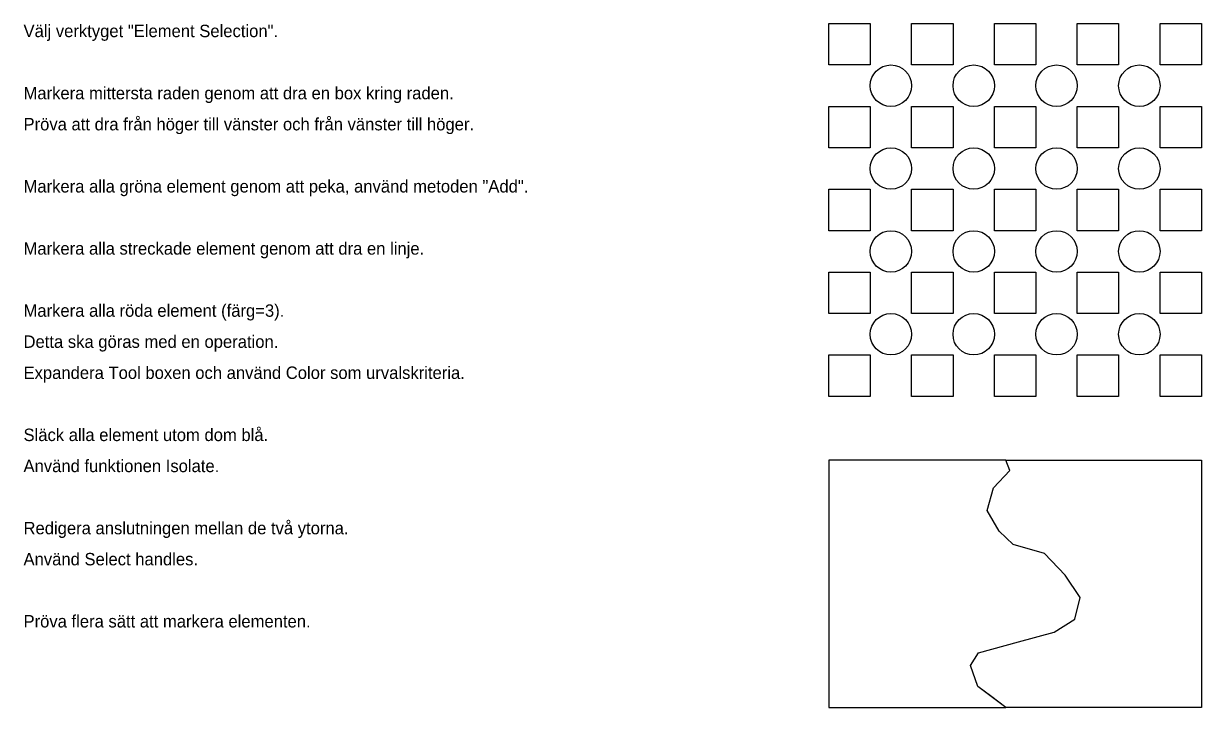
# Model space of a CAD drawing. Extents: x 1517706.2 to 1517734.6, y 6495359.5 to 6495376.
import ezdxf

# ---------------------------------------------------------------- set-up
doc = ezdxf.new("R2010")
doc.units = 0
doc.layers.add('Instruktioner', color=7, linetype='Continuous')
doc.layers.add('Lager 1', color=7, linetype='Continuous')

msp = doc.modelspace()

# ---------------------------------------------------------------- linework, layer by layer
at = {"layer": 'Lager 1'}
for points in [[(1517725.643, 6495375.967), (1517726.643, 6495375.967), (1517726.643, 6495374.967), (1517725.643, 6495374.967)], [(1517727.643, 6495375.967), (1517728.643, 6495375.967), (1517728.643, 6495374.967), (1517727.643, 6495374.967)], [(1517729.643, 6495375.967), (1517730.643, 6495375.967), (1517730.643, 6495374.967), (1517729.643, 6495374.967)], [(1517731.643, 6495375.967), (1517732.643, 6495375.967), (1517732.643, 6495374.967), (1517731.643, 6495374.967)], [(1517733.643, 6495375.967), (1517734.643, 6495375.967), (1517734.643, 6495374.967), (1517733.643, 6495374.967)], [(1517725.643, 6495373.967), (1517726.643, 6495373.967), (1517726.643, 6495372.967), (1517725.643, 6495372.967)], [(1517727.643, 6495373.967), (1517728.643, 6495373.967), (1517728.643, 6495372.967), (1517727.643, 6495372.967)], [(1517729.643, 6495373.967), (1517730.643, 6495373.967), (1517730.643, 6495372.967), (1517729.643, 6495372.967)], [(1517731.643, 6495373.967), (1517732.643, 6495373.967), (1517732.643, 6495372.967), (1517731.643, 6495372.967)], [(1517733.643, 6495373.967), (1517734.643, 6495373.967), (1517734.643, 6495372.967), (1517733.643, 6495372.967)], [(1517725.643, 6495371.967), (1517726.643, 6495371.967), (1517726.643, 6495370.967), (1517725.643, 6495370.967)], [(1517727.643, 6495371.967), (1517728.643, 6495371.967), (1517728.643, 6495370.967), (1517727.643, 6495370.967)], [(1517729.643, 6495371.967), (1517730.643, 6495371.967), (1517730.643, 6495370.967), (1517729.643, 6495370.967)], [(1517731.643, 6495371.967), (1517732.643, 6495371.967), (1517732.643, 6495370.967), (1517731.643, 6495370.967)], [(1517733.643, 6495371.967), (1517734.643, 6495371.967), (1517734.643, 6495370.967), (1517733.643, 6495370.967)], [(1517725.643, 6495369.967), (1517726.643, 6495369.967), (1517726.643, 6495368.967), (1517725.643, 6495368.967)], [(1517727.643, 6495369.967), (1517728.643, 6495369.967), (1517728.643, 6495368.967), (1517727.643, 6495368.967)], [(1517729.643, 6495369.967), (1517730.643, 6495369.967), (1517730.643, 6495368.967), (1517729.643, 6495368.967)], [(1517731.643, 6495369.967), (1517732.643, 6495369.967), (1517732.643, 6495368.967), (1517731.643, 6495368.967)], [(1517733.643, 6495369.967), (1517734.643, 6495369.967), (1517734.643, 6495368.967), (1517733.643, 6495368.967)], [(1517725.643, 6495367.967), (1517726.643, 6495367.967), (1517726.643, 6495366.967), (1517725.643, 6495366.967)], [(1517727.643, 6495367.967), (1517728.643, 6495367.967), (1517728.643, 6495366.967), (1517727.643, 6495366.967)], [(1517729.643, 6495367.967), (1517730.643, 6495367.967), (1517730.643, 6495366.967), (1517729.643, 6495366.967)], [(1517731.643, 6495367.967), (1517732.643, 6495367.967), (1517732.643, 6495366.967), (1517731.643, 6495366.967)], [(1517733.643, 6495367.967), (1517734.643, 6495367.967), (1517734.643, 6495366.967), (1517733.643, 6495366.967)], [(1517729.916, 6495365.426), (1517725.643, 6495365.426), (1517725.643, 6495359.459), (1517729.916, 6495359.459), (1517729.241, 6495359.966), (1517729.067, 6495360.471), (1517729.26, 6495360.775), (1517730.224, 6495361.041), (1517731.088, 6495361.28), (1517731.584, 6495361.586), (1517731.716, 6495362.109), (1517731.354, 6495362.65), (1517730.856, 6495363.177), (1517730.096, 6495363.394), (1517729.756, 6495363.716), (1517729.471, 6495364.212), (1517729.622, 6495364.764), (1517730.014, 6495365.18)], [(1517729.916, 6495365.426), (1517734.643, 6495365.426), (1517734.643, 6495359.459), (1517729.916, 6495359.459), (1517729.579, 6495359.713), (1517729.241, 6495359.966), (1517729.067, 6495360.471), (1517729.26, 6495360.775), (1517730.224, 6495361.041), (1517731.088, 6495361.28), (1517731.584, 6495361.586), (1517731.716, 6495362.109), (1517731.354, 6495362.65), (1517730.856, 6495363.177), (1517730.096, 6495363.394), (1517729.756, 6495363.716), (1517729.471, 6495364.212), (1517729.622, 6495364.764), (1517730.014, 6495365.18)]]:
    msp.add_lwpolyline(points, close=True, dxfattribs=at)
for centre in [(1517727.143, 6495374.467), (1517729.143, 6495374.467), (1517731.143, 6495374.467), (1517733.143, 6495374.467), (1517727.143, 6495372.467), (1517729.143, 6495372.467), (1517731.143, 6495372.467), (1517733.143, 6495372.467), (1517727.143, 6495370.467), (1517729.143, 6495370.467), (1517731.143, 6495370.467), (1517733.143, 6495370.467), (1517727.143, 6495368.467), (1517729.143, 6495368.467), (1517731.143, 6495368.467), (1517733.143, 6495368.467)]:
    msp.add_circle(centre, 0.5, dxfattribs=at)

# ---------------------------------------------------------------- texts
at = {"layer": 'Instruktioner'}
for s, p in [('Välj verktyget "Element Selection".', (1517706.194, 6495375.639)), ('Markera mittersta raden genom att dra en box kring raden.', (1517706.194, 6495374.139)), ('Pröva att dra från höger till vänster och från vänster till höger.', (1517706.194, 6495373.389)), ('Markera alla gröna element genom att peka, använd metoden "Add".', (1517706.194, 6495371.889)), ('Markera alla streckade element genom att dra en linje.', (1517706.194, 6495370.389)), ('Markera alla röda element (färg=3).', (1517706.194, 6495368.889)), ('Detta ska göras med en operation. ', (1517706.194, 6495368.139)), ('Expandera Tool boxen och använd Color som urvalskriteria.', (1517706.194, 6495367.389)), ('Släck alla element utom dom blå.', (1517706.194, 6495365.889)), ('Använd funktionen Isolate.', (1517706.194, 6495365.139)), ('Redigera anslutningen mellan de två ytorna.', (1517706.194, 6495363.639)), ('Använd Select handles.', (1517706.194, 6495362.889)), ('Pröva flera sätt att markera elementen. ', (1517706.194, 6495361.389))]:
    msp.add_text(s, height=0.3, dxfattribs=at).set_placement(p)

doc.saveas('drawing.dxf')
